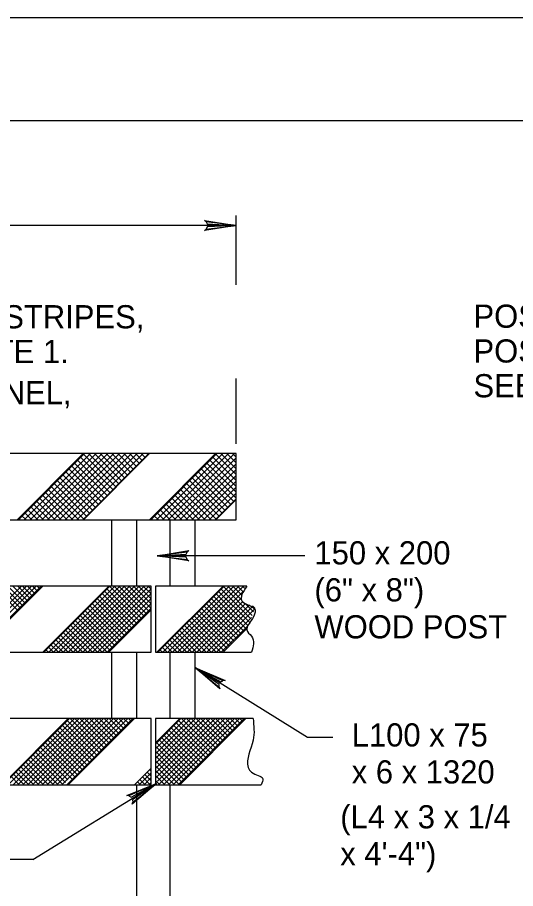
# Model space of a CAD drawing. Extents: x -4 to 901, y -468 to 720.
# Drawn here: x 517.4 to 589.7, y 593.8 to 720 of the extents above; entities that cross this region are included whole.
import ezdxf

# ---------------------------------------------------------------- set-up
doc = ezdxf.new("R2010")
doc.units = 0
for name, color, linetype in [('1', 7, 'Continuous'), ('2', 7, 'Continuous'), ('3', 7, 'Continuous'), ('PLT-BNDY', 7, 'Continuous')]:
    doc.layers.add(name, color=color, linetype=linetype)

msp = doc.modelspace()

# ---------------------------------------------------------------- linework, layer by layer
at = {"layer": '1'}
msp.add_lwpolyline([(822.258, 141.027875), (822.258, 705.027875), (36.258, 705.027875), (36.258, 141.027875), (822.258, 141.027875), (822.258, 167.386875), (622.258, 167.386875), (622.258, 232.064375), (822.258, 232.064375), (822.258, 261.027875), (622.258, 261.027875), (622.258, 141.027875), (701.0595, 141.027875), (701.0595, 167.386875), (701.0595, 141.027875), (778.0595, 141.027875), (778.0595, 167.386875), (778.0595, 155.070375), (822.258, 155.070375)], dxfattribs=at)
at = {"layer": '2'}
for p, q in [((549.1045, 681.251125), (549.1045, 691.305125)), ((549.1045, 689.865125), (405.1045, 689.865125)), ((549.1045, 658.235125), (549.1045, 667.691125)), ((517.3385, 647.195125), (526.9385, 656.795125)), ((526.95, 647.195125), (536.55, 656.795125)), ((536.5385, 647.195125), (546.1385, 656.795125)), ((546.15, 647.195125), (549.1045, 650.149625)), ((511.4525, 627.995125), (521.0525, 637.595125)), ((521.0525, 627.995125), (530.6525, 637.595125)), ((537.6165, 627.995125), (547.2165, 637.595125)), ((530.6525, 627.995125), (536.7925, 634.135125)), ((547.2165, 627.995125), (550.7205, 631.499125)), ((515.1665, 608.795125), (524.7665, 618.395125)), ((515.1665, 608.795125), (524.7665, 618.395125)), ((515.1665, 608.795125), (524.7665, 618.395125)), ((515.1665, 608.795125), (524.7665, 618.395125)), ((515.1665, 608.795125), (524.7665, 618.395125)), ((515.1665, 608.795125), (524.7665, 618.395125)), ((515.1665, 608.795125), (524.7665, 618.395125)), ((515.1665, 608.795125), (524.7665, 618.395125)), ((520.3045, 613.933125), (524.7665, 618.395125)), ((524.7665, 608.795125), (534.3665, 618.395125)), ((537.4185, 614.881125), (540.9325, 618.395125)), ((540.9325, 608.795125), (550.5325, 618.395125)), ((534.3885, 608.795125), (536.7925, 611.199125)), ((519.64075, 597.967625), (498.79225, 597.967625))]:
    msp.add_line(p, q, dxfattribs=at)
for points in [[(544.7445, 690.413125), (544.9085, 690.097125), (549.1045, 689.865125), (544.7445, 690.413125), (544.5225, 690.603125), (549.1045, 689.865125), (544.9105, 689.657125), (544.7585, 689.345125), (549.1045, 689.865125), (544.5225, 689.137125), (544.7585, 689.345125)], [(517.52625, 647.195125), (527.12625, 656.795125)], [(518.37475, 647.195125), (527.97475, 656.795125)], [(519.22325, 647.195125), (528.82325, 656.795125)], [(520.07175, 647.195125), (529.67175, 656.795125)], [(520.92025, 647.195125), (530.52025, 656.795125)], [(521.76875, 647.195125), (531.36875, 656.795125)], [(522.61725, 647.195125), (532.21725, 656.795125)], [(523.46575, 647.195125), (533.06575, 656.795125)], [(524.31425, 647.195125), (533.91425, 656.795125)], [(525.16325, 647.195125), (534.76325, 656.795125)], [(526.01175, 647.195125), (535.61175, 656.795125)], [(526.86025, 647.195125), (536.46025, 656.795125)], [(531.7055, 651.950875), (526.9055, 656.750875)], [(532.12975, 652.375125), (527.70975, 656.795125)], [(532.554, 652.799375), (528.55825, 656.795125)], [(532.97825, 653.223625), (529.40675, 656.795125)], [(533.4025, 653.647875), (530.25525, 656.795125)], [(533.82675, 654.072125), (531.10375, 656.795125)], [(534.251, 654.496375), (531.95225, 656.795125)], [(534.67525, 654.920625), (532.80075, 656.795125)], [(535.0995, 655.344875), (533.64925, 656.795125)], [(535.52375, 655.769125), (534.49775, 656.795125)], [(535.948, 656.193375), (535.34625, 656.795125)], [(536.37225, 656.617625), (536.19475, 656.795125)], [(536.72625, 647.195125), (546.32625, 656.795125)], [(537.57475, 647.195125), (547.17475, 656.795125)], [(538.42325, 647.195125), (548.02325, 656.795125)], [(539.27175, 647.195125), (548.87175, 656.795125)], [(549.1045, 653.751875), (546.1055, 656.750875)], [(549.1045, 654.600375), (546.90975, 656.795125)], [(549.1045, 655.448875), (547.75825, 656.795125)], [(549.1045, 656.297375), (548.60675, 656.795125)], [(530.4325, 650.677875), (525.6325, 655.477875)], [(530.857, 651.102375), (526.057, 655.902375)], [(531.28125, 651.526625), (526.48125, 656.326625)], [(540.12025, 647.195125), (549.1045, 656.179375)], [(549.1045, 651.205875), (544.8325, 655.477875)], [(549.1045, 652.054875), (545.257, 655.902375)], [(549.1045, 652.903375), (545.68125, 656.326625)], [(529.15975, 649.405125), (524.35975, 654.205125)], [(529.584, 649.829375), (524.784, 654.629375)], [(530.00825, 650.253625), (525.20825, 655.053625)], [(540.96875, 647.195125), (549.1045, 655.330875)], [(541.81725, 647.195125), (549.1045, 654.482375)], [(548.338, 649.426875), (543.55975, 654.205125)], [(548.76225, 649.851125), (543.984, 654.629375)], [(549.1045, 650.357375), (544.40825, 655.053625)], [(527.887, 648.132375), (523.087, 652.932375)], [(528.31125, 648.556625), (523.51125, 653.356625)], [(528.7355, 648.980875), (523.9355, 653.780875)], [(547.06525, 648.154125), (542.287, 652.932375)], [(542.66575, 647.195125), (549.1045, 653.633875)], [(547.4895, 648.578375), (542.71125, 653.356625)], [(547.91375, 649.002625), (543.1355, 653.780875)], [(526.27875, 647.195125), (521.81425, 651.659625)], [(527.0385, 647.283875), (522.2385, 652.083875)], [(527.46275, 647.708125), (522.66275, 652.508125)], [(545.47875, 647.195125), (541.01425, 651.659625)], [(546.21675, 647.305625), (541.4385, 652.083875)], [(546.641, 647.729875), (541.86275, 652.508125)], [(543.51425, 647.195125), (549.1045, 652.785375)], [(544.36325, 647.195125), (549.1045, 651.936375)], [(523.73325, 647.195125), (520.5415, 650.386875)], [(524.58175, 647.195125), (520.96575, 650.811125)], [(525.43025, 647.195125), (521.39, 651.235375)], [(542.93325, 647.195125), (539.7415, 650.386875)], [(543.78175, 647.195125), (540.16575, 650.811125)], [(544.63025, 647.195125), (540.59, 651.235375)], [(545.21175, 647.195125), (549.1045, 651.087875)], [(521.18775, 647.195125), (519.26875, 649.114125)], [(522.03625, 647.195125), (519.693, 649.538375)], [(522.88475, 647.195125), (520.11725, 649.962625)], [(540.38775, 647.195125), (538.46875, 649.114125)], [(541.23625, 647.195125), (538.893, 649.538375)], [(542.08475, 647.195125), (539.31725, 649.962625)], [(546.06025, 647.195125), (549.1045, 650.239375)], [(518.64175, 647.195125), (517.99575, 647.841125)], [(519.49025, 647.195125), (518.42, 648.265375)], [(520.33925, 647.195125), (518.8445, 648.689875)], [(537.84175, 647.195125), (537.19575, 647.841125)], [(538.69025, 647.195125), (537.62, 648.265375)], [(539.53925, 647.195125), (538.0445, 648.689875)], [(517.79325, 647.195125), (517.5715, 647.416875)], [(531.1045, 637.595125), (531.1045, 647.195125)], [(534.7045, 637.595125), (534.7045, 647.195125), (539.5045, 647.195125), (539.5045, 637.595125)], [(536.99325, 647.195125), (536.7715, 647.416875)], [(543.1045, 647.195125), (543.1045, 637.595125)], [(542.0205, 641.457125), (541.8585, 641.773125), (537.6625, 642.005125), (542.0205, 641.457125), (542.2445, 641.267125), (537.6625, 642.005125), (541.8565, 642.213125), (542.0085, 642.525125), (537.6625, 642.005125), (542.2445, 642.733125), (542.0085, 642.525125)], [(559.0645, 642.005125), (537.6625, 642.005125)], [(508.396, 627.995125), (517.996, 637.595125)], [(509.103, 627.995125), (518.703, 637.595125)], [(509.8105, 627.995125), (519.4105, 637.595125)], [(510.5175, 627.995125), (520.1175, 637.595125)], [(511.2245, 627.995125), (520.8245, 637.595125)], [(517.4765, 634.019375), (513.90075, 637.595125)], [(517.83, 634.372875), (514.60775, 637.595125)], [(518.1835, 634.726375), (515.31475, 637.595125)], [(518.537, 635.079875), (516.02175, 637.595125)], [(518.8905, 635.433375), (516.72875, 637.595125)], [(519.24425, 635.787125), (517.43625, 637.595125)], [(519.59775, 636.140625), (518.14325, 637.595125)], [(519.95125, 636.494125), (518.85025, 637.595125)], [(520.30475, 636.847625), (519.55725, 637.595125)], [(520.6585, 637.201375), (520.26475, 637.595125)], [(521.21775, 627.995125), (530.81775, 637.595125)], [(521.92475, 627.995125), (531.52475, 637.595125)], [(522.63225, 627.995125), (532.23225, 637.595125)], [(523.33925, 627.995125), (532.93925, 637.595125)], [(524.04625, 627.995125), (533.64625, 637.595125)], [(524.75325, 627.995125), (534.35325, 637.595125)], [(525.46075, 627.995125), (535.06075, 637.595125)], [(526.16775, 627.995125), (535.76775, 637.595125)], [(526.87475, 627.995125), (536.47475, 637.595125)], [(527.58175, 627.995125), (536.7925, 637.205875)], [(528.28875, 627.995125), (536.7925, 636.498875)], [(534.41625, 631.759125), (529.61625, 636.559125)], [(534.77, 632.112875), (529.97, 636.912875)], [(535.1235, 632.466375), (530.3235, 637.266375)], [(535.477, 632.819875), (530.677, 637.619875)], [(535.8305, 633.173375), (531.40875, 637.595125)], [(536.184, 633.526875), (532.11575, 637.595125)], [(536.53775, 633.880625), (532.82325, 637.595125)], [(536.7925, 634.332875), (533.53025, 637.595125)], [(536.7925, 635.039875), (534.23725, 637.595125)], [(536.7925, 635.746875), (534.94425, 637.595125)], [(536.7925, 636.453875), (535.65125, 637.595125)], [(536.7925, 637.161375), (536.35875, 637.595125)], [(550.6485, 637.595125), (537.4185, 637.595125), (537.4185, 627.995125), (551.3465, 627.995125)], [(537.77425, 627.995125), (547.37425, 637.595125)], [(538.48125, 627.995125), (548.08125, 637.595125)], [(539.18875, 627.995125), (548.78875, 637.595125)], [(539.89575, 627.995125), (549.49575, 637.595125)], [(540.60275, 627.995125), (550.20275, 637.595125)], [(541.30975, 627.995125), (550.083, 636.768375)], [(550.84125, 631.842875), (546.15275, 636.531375)], [(551.03475, 632.356875), (546.5065, 636.885125)], [(551.2405, 632.858125), (546.86, 637.238625)], [(551.44975, 633.355875), (547.2135, 637.592125)], [(549.9425, 635.570375), (547.9175, 637.595125)], [(549.971, 636.248375), (548.6245, 637.595125)], [(550.10275, 636.824375), (549.332, 637.595125)], [(550.33675, 637.297375), (550.039, 637.595125)], [(533.35575, 630.698625), (528.55575, 635.498625)], [(533.70925, 631.052125), (528.90925, 635.852125)], [(528.99625, 627.995125), (536.7925, 635.791375)], [(534.06275, 631.405625), (529.26275, 636.205625)], [(542.01725, 627.995125), (549.94225, 635.920125)], [(542.72425, 627.995125), (550.02675, 635.297625)], [(549.912, 630.651125), (545.09225, 635.470875)], [(550.2655, 631.004625), (545.44575, 635.824375)], [(550.619, 631.358125), (545.79925, 636.177875)], [(531.9415, 629.284375), (527.1415, 634.084375)], [(532.295, 629.637875), (527.495, 634.437875)], [(532.6485, 629.991375), (527.8485, 634.791375)], [(533.00225, 630.345125), (528.20225, 635.145125)], [(529.70325, 627.995125), (536.7925, 635.084375)], [(530.41025, 627.995125), (536.7925, 634.377375)], [(543.43125, 627.995125), (550.497, 635.060875)], [(548.49775, 629.236875), (543.678, 634.056625)], [(548.85125, 629.590375), (544.0315, 634.410125)], [(544.13825, 627.995125), (551.0405, 634.897375)], [(549.20475, 629.943875), (544.385, 634.763625)], [(549.5585, 630.297625), (544.73875, 635.117375)], [(544.84525, 627.995125), (551.55575, 634.705625)], [(545.55275, 627.995125), (551.7965, 634.238875)], [(551.6535, 633.859125), (550.4285, 635.084125)], [(551.82675, 634.392875), (551.47475, 634.744875)], [(530.40225, 627.995125), (525.72725, 632.670125)], [(530.88075, 628.223625), (526.08075, 633.023625)], [(531.23425, 628.577125), (526.43425, 633.377125)], [(531.588, 628.930875), (526.788, 633.730875)], [(547.437, 628.176125), (542.61725, 632.995875)], [(547.7905, 628.529625), (542.97075, 633.349375)], [(548.14425, 628.883375), (543.3245, 633.703125)], [(546.25975, 627.995125), (551.326, 633.061375)], [(528.28075, 627.995125), (524.6665, 631.609375)], [(528.98825, 627.995125), (525.02025, 631.963125)], [(529.69525, 627.995125), (525.37375, 632.316625)], [(544.7895, 627.995125), (541.203, 631.581625)], [(545.497, 627.995125), (541.55675, 631.935375)], [(546.204, 627.995125), (541.91025, 632.288875)], [(546.911, 627.995125), (542.26375, 632.642375)], [(546.96675, 627.995125), (550.8565, 631.884875)], [(525.45275, 627.995125), (523.2525, 630.195375)], [(526.15975, 627.995125), (523.606, 630.548875)], [(526.86675, 627.995125), (523.9595, 630.902375)], [(527.57375, 627.995125), (524.313, 631.255875)], [(541.9615, 627.995125), (539.789, 630.167625)], [(542.6685, 627.995125), (540.1425, 630.521125)], [(543.3755, 627.995125), (540.496, 630.874625)], [(544.0825, 627.995125), (540.8495, 631.228125)], [(523.33125, 627.995125), (522.19175, 629.134625)], [(524.03825, 627.995125), (522.54525, 629.488125)], [(524.74525, 627.995125), (522.89875, 629.841625)], [(539.84, 627.995125), (538.72825, 629.106875)], [(540.547, 627.995125), (539.08175, 629.460375)], [(541.254, 627.995125), (539.43525, 629.813875)], [(521.91675, 627.995125), (521.4845, 628.427375)], [(522.62425, 627.995125), (521.83825, 628.781125)], [(531.1045, 618.395125), (531.1045, 627.995125)], [(534.7045, 618.395125), (534.7045, 627.995125)], [(538.4255, 627.995125), (538.021, 628.399625)], [(539.133, 627.995125), (538.37475, 628.753375)], [(539.5045, 627.995125), (539.5045, 618.395125)], [(543.1045, 627.995125), (543.1045, 618.395125)], [(563.157019, 615.634574), (559.4665, 615.634574), (543.2345, 625.734574)], [(546.6465, 622.966574), (546.6765, 623.320574), (543.2345, 625.734574), (546.6465, 622.966574), (546.7365, 622.686574), (543.2345, 625.734574), (546.9045, 623.694574), (547.1985, 623.878574), (543.2345, 625.734574), (547.5105, 623.930574), (547.1985, 623.878574)], [(515.34275, 608.795125), (524.94275, 618.395125)], [(516.04975, 608.795125), (525.64975, 618.395125)], [(516.75675, 608.795125), (526.35675, 618.395125)], [(517.46375, 608.795125), (527.06375, 618.395125)], [(518.17075, 608.795125), (527.77075, 618.395125)], [(518.87775, 608.795125), (528.47775, 618.395125)], [(519.58475, 608.795125), (529.18475, 618.395125)], [(520.29225, 608.795125), (529.89225, 618.395125)], [(520.99925, 608.795125), (530.59925, 618.395125)], [(521.70625, 608.795125), (531.30625, 618.395125)], [(522.41325, 608.795125), (532.01325, 618.395125)], [(523.12075, 608.795125), (532.72075, 618.395125)], [(523.82775, 608.795125), (533.42775, 618.395125)], [(528.987, 613.015875), (524.18725, 617.815625)], [(524.53475, 608.795125), (534.13475, 618.395125)], [(529.3405, 613.369375), (524.54075, 618.169125)], [(529.694, 613.722875), (525.02175, 618.395125)], [(530.0475, 614.076375), (525.72875, 618.395125)], [(530.401, 614.429875), (526.43575, 618.395125)], [(530.7545, 614.783375), (527.14275, 618.395125)], [(531.10825, 615.137125), (527.85025, 618.395125)], [(531.46175, 615.490625), (528.55725, 618.395125)], [(531.8155, 615.844375), (529.26475, 618.395125)], [(532.169, 616.197875), (529.97175, 618.395125)], [(532.5225, 616.551375), (530.67875, 618.395125)], [(532.876, 616.904875), (531.38575, 618.395125)], [(533.2295, 617.258375), (532.09275, 618.395125)], [(533.583, 617.611875), (532.79975, 618.395125)], [(533.9365, 617.965375), (533.50675, 618.395125)], [(534.29025, 618.319125), (534.21425, 618.395125)], [(551.5785, 618.395125), (537.4185, 618.395125), (537.4185, 608.795125), (552.7385, 608.795125)], [(537.4185, 613.997875), (541.81575, 618.395125)], [(537.4185, 613.290875), (542.52275, 618.395125)], [(537.4185, 612.583875), (543.22975, 618.395125)], [(537.4185, 611.876875), (543.93675, 618.395125)], [(537.4185, 611.169875), (544.64375, 618.395125)], [(537.4185, 610.462875), (545.35075, 618.395125)], [(537.4185, 609.755375), (546.05825, 618.395125)], [(537.4185, 614.704875), (541.10875, 618.395125)], [(537.7045, 609.334375), (546.76525, 618.395125)], [(537.87225, 608.795125), (547.47225, 618.395125)], [(538.57925, 608.795125), (548.17925, 618.395125)], [(539.28675, 608.795125), (548.88675, 618.395125)], [(539.99375, 608.795125), (549.59375, 618.395125)], [(545.153, 613.015875), (540.35325, 617.815625)], [(540.70075, 608.795125), (550.30075, 618.395125)], [(545.5065, 613.369375), (540.70675, 618.169125)], [(545.86, 613.722875), (541.18775, 618.395125)], [(546.2135, 614.076375), (541.89475, 618.395125)], [(546.56725, 614.430125), (542.60225, 618.395125)], [(546.92075, 614.783625), (543.30925, 618.395125)], [(547.2745, 615.137375), (544.01675, 618.395125)], [(547.628, 615.490875), (544.72375, 618.395125)], [(547.9815, 615.844375), (545.43075, 618.395125)], [(548.335, 616.197875), (546.13775, 618.395125)], [(548.6885, 616.551375), (546.84475, 618.395125)], [(549.042, 616.904875), (547.55175, 618.395125)], [(549.3955, 617.258375), (548.25875, 618.395125)], [(549.749, 617.611875), (548.96575, 618.395125)], [(550.1025, 617.965375), (549.67275, 618.395125)], [(550.45625, 618.319125), (550.38025, 618.395125)], [(527.5725, 611.601375), (522.77275, 616.401125)], [(527.92625, 611.955125), (523.1265, 616.754875)], [(528.27975, 612.308625), (523.48, 617.108375)], [(528.6335, 612.662375), (523.83375, 617.462125)], [(543.7385, 611.601375), (538.93875, 616.401125)], [(544.09225, 611.955125), (539.2925, 616.754875)], [(544.44575, 612.308625), (539.646, 617.108375)], [(544.7995, 612.662375), (539.99975, 617.462125)], [(526.1585, 610.187375), (521.35875, 614.987125)], [(526.512, 610.540875), (521.71225, 615.340625)], [(526.8655, 610.894375), (522.06575, 615.694125)], [(527.219, 611.247875), (522.41925, 616.047625)], [(542.3245, 610.187375), (537.52475, 614.987125)], [(542.678, 610.540875), (537.87825, 615.340625)], [(543.0315, 610.894375), (538.23175, 615.694125)], [(543.385, 611.247875), (538.58525, 616.047625)], [(524.72225, 609.502125), (520.298, 613.926375)], [(525.4515, 609.480375), (520.65175, 614.280125)], [(525.805, 609.833875), (521.00525, 614.633625)], [(541.971, 609.833875), (537.4185, 614.386375)], [(522.60125, 608.795125), (518.884, 612.512375)], [(523.30825, 608.795125), (519.2375, 612.865875)], [(524.01525, 608.795125), (519.591, 613.219375)], [(524.36875, 609.148625), (519.9445, 613.572875)], [(541.6175, 609.480375), (537.4185, 613.679375)], [(541.264, 609.126375), (537.4185, 612.971875)], [(520.48025, 608.795125), (517.8235, 611.451875)], [(521.18725, 608.795125), (518.177, 611.805375)], [(521.89425, 608.795125), (518.5305, 612.158875)], [(540.88825, 608.795125), (537.4185, 612.264875)], [(540.18125, 608.795125), (537.4185, 611.557875)], [(517.65175, 608.795125), (516.40925, 610.037625)], [(518.35875, 608.795125), (516.76275, 610.391125)], [(519.06575, 608.795125), (517.11625, 610.744625)], [(519.77275, 608.795125), (517.46975, 611.098125)], [(535.04375, 608.795125), (536.7925, 610.543875)], [(536.64625, 608.795125), (535.5175, 609.923875)], [(536.7925, 609.355875), (535.871, 610.277375)], [(536.7925, 610.062875), (536.2245, 610.630875)], [(536.7925, 610.769875), (536.578, 610.984375)], [(539.47425, 608.795125), (537.4185, 610.850875)], [(538.76725, 608.795125), (537.4185, 610.143875)], [(519.64075, 597.967625), (537.5585, 609.003125)], [(533.5605, 607.183125), (533.8645, 606.999125), (537.5585, 609.003125), (533.5605, 607.183125), (533.2705, 607.229125), (537.5585, 609.003125), (534.0965, 606.627125), (534.1305, 606.281125), (537.5585, 609.003125), (534.0385, 605.981125), (534.1305, 606.281125)], [(534.7045, 584.369125), (534.7045, 608.795125)], [(535.23175, 608.795125), (534.81, 609.216875)], [(535.93875, 608.795125), (535.1635, 609.570375)], [(535.75075, 608.795125), (536.7925, 609.836875)], [(536.45825, 608.795125), (536.7925, 609.129375)], [(537.16525, 608.795125), (537.26975, 608.899625)], [(538.06025, 608.795125), (537.4185, 609.436875)], [(539.5045, 608.795125), (539.5045, 583.441125)]]:
    msp.add_lwpolyline(points, dxfattribs=at)
for points in [[(405.1045, 656.795125), (405.1045, 647.195125), (549.1045, 647.195125), (549.1045, 656.795125)], [(405.1045, 637.595125), (405.1045, 627.995125), (536.7925, 627.995125), (536.7925, 637.595125)], [(405.1045, 618.395125), (405.1045, 608.795125), (536.7925, 608.795125), (536.7925, 618.395125)]]:
    msp.add_lwpolyline(points, close=True, dxfattribs=at)
for points in [[(550.6485, 637.595125), (549.9525, 635.439125), (551.8105, 634.277125), (550.8825, 631.957125), (550.6485, 631.259125), (551.3465, 630.331125), (551.3465, 627.995125)], [(551.5785, 618.395125), (551.5785, 615.243125), (550.8825, 611.297125), (551.3465, 610.601125), (552.9705, 609.671125), (552.7385, 608.795125)]]:
    msp.add_spline(points, degree=3, dxfattribs=at)
at = {"layer": 'PLT-BNDY'}
msp.add_lwpolyline([(-3.742, 720.027875), (837.258, 720.027875), (837.258, 126.027875), (-3.742, 126.027875)], close=True, dxfattribs=at)

# ---------------------------------------------------------------- texts
at = {"layer": '1'}
for s, p in [('(L4 x 3 x 1/4', (564.221858, 602.478108)), ('x 4\'-4")', (564.221858, 597.118108))]:
    msp.add_text(s, height=3.36, dxfattribs=at).set_placement(p)
at = {"layer": '3'}
for s, height, p in [('ALTERNATE RED AND WHITE STRIPES,', 3.359988, (450.4265, 674.959125)), ('POST CLIP AND', 3.359988, (583.5405, 675.041875)), ('TRAFFIC SIDE ONLY, SEE NOTE 1.', 3.359988, (450.4265, 669.919125)), ('POST CLIP BOLT,', 3.359988, (583.5405, 670.001875)), ('SEE DETAILS.', 3.359988, (583.5405, 664.961875)), ('EXTRUDED ALUMINUM CHANNEL,', 3.359988, (451.3425, 663.965125)), ('150 x 200', 3.36, (560.471, 640.737375)), ('(6" x 8")', 3.36, (560.471, 635.377375)), ('WOOD POST', 3.36, (560.471, 630.017375)), ('L100 x 75', 3.36, (565.883061, 614.343162)), ('x 6 x 1320', 3.36, (565.883061, 608.983162))]:
    msp.add_text(s, height=height, dxfattribs=at).set_placement(p)

doc.saveas('drawing.dxf')
